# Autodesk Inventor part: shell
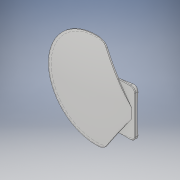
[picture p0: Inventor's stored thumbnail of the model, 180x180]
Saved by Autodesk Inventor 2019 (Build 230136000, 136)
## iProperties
Created: 2021-03
Part Number: shell
Material: 一般
Document SubType Name: Modeling
Designer: kikut
Density: 1 g/cm^3
Appearance: 既定
Author: kikut
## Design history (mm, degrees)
sketch "スケッチ2"
  geometry: L1 (-300, 0)-(300, 0); A1 r 300 centre (0, 0) between (300, 0) and (-300, 0); 1 further point
  constraints: 2 end point, 2 point on circle, 1 centre point, 1 coincident, 1 horizontal
  dimensions: "d1" = 300 radius of A1
revolve "回転1" sketch "スケッチ2" stored, may be unused: angle "d2" = 180 deg
sketch "スケッチ3"
  geometry: L1 (500, 288)-(-500, 288); L2 (-500, 288)-(-500, -512); L3 (-500, -512)-(500, -512); L4 (500, -512)-(500, 288); L5 (0, -580)-(0, 540) reference; 1 further point
  constraints: 8 end point, 2 parallel, 1 horizontal, 1 perpendicular, 1 other
  dimensions: "d3" = 288 distance from line of L1 point (0, 0); "d4" = 800 distance of L1.end L2.end; "d5" = 1000 distance of L2.end L3.end
extrude "押し出し1" cut sketch "スケッチ3" stored distance "d7" = 800; taper "d8" = 0 deg
sketch "スケッチ6"
  geometry: C1 r 80 at (0, 0); C2 r 200 at (0, 0); 1 further point
  constraints: 2 centre point, 2 coincident
  dimensions: "d9" = 160 diameter of C1; "d10" = 400 diameter of C2
extrude "押し出し2" cut sketch "スケッチ6" distance "d11" = 100; taper "d12" = 0 deg
sketch "スケッチ7"
  geometry: L1 (-13.892, 78.785)-(-70, 0); L2 (-70, 0)-(-13.892, -78.785); C1 r 120 at (0, 0); A1 r 80 centre (0, 0) between (-13.892, -78.785) and (-13.892, 78.785) reference; A2 r 80 centre (0, 0) between (-13.892, -78.785) and (-13.892, 78.785); 1 further point
  constraints: 4 end point, 4 point on circle, 2 centre point, 2 coincident
  dimensions: "d13" = 0 horizontal distance of L2.end L1.start; "d14" = 160 deg dimension on point (0, 0) L2.end L1.start; "d15" = 70 distance of point (0, 0) L1.end; "d16" = 240 diameter of C1
extrude "押し出し3" cut sketch "スケッチ7" distance "d17" = 100; taper "d18" = 0 deg
sketch "スケッチ8"
  geometry: L1 (-30, -40)-(-70, -40); L2 (-70, -40)-(-70, 40); L3 (-70, 40)-(-30, 40); L4 (-30, 40)-(-30, -40); L5 (110, 0)-(-100, 0) reference; 1 further point
  constraints: 8 end point, 2 parallel, 1 horizontal, 1 perpendicular, 1 other
  dimensions: "d19" = 80 distance of L1.end L2.end; "d20" = 70 distance from line of point (0, 0) L2; "d21" = 40 distance of L1.start L1.end
extrude "押し出し4" join sketch "スケッチ8" distance "d22" = 5; taper "d23" = 0 deg
sketch "スケッチ9"
  geometry: L1 (0, 298)-(0, -298); A1 r 298 centre (0, 0) between (0, 298) and (0, -298); 1 further point
  constraints: 2 end point, 2 point on circle, 1 centre point, 1 coincident, 1 vertical
  dimensions: "d24" = 298 radius of A1
revolve "回転2" sketch "スケッチ9" stored, may be unused: angle "d25" = 90 deg
fillet "フィレット1" dims "d26" = 20
fillet "フィレット2" dims "d27" = 8
fillet "フィレット3" dims "d28" = 1
node "ソリッド1"
